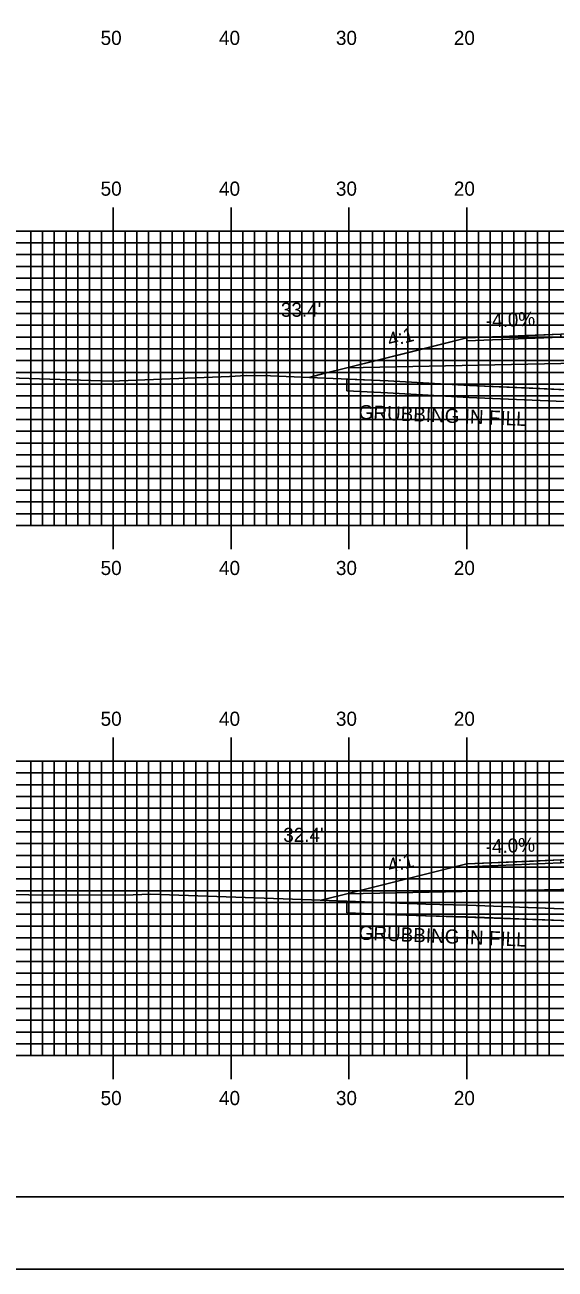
# Model space of a CAD drawing. Extents: x 1772022 to 1772366, y 442591 to 442811.
# Drawn here: x 1772130.6 to 1772175.6, y 442590.5 to 442696.2 of the extents above; entities that cross this region are included whole.
import ezdxf

# ---------------------------------------------------------------- set-up
doc = ezdxf.new("R2010")
doc.units = 0
for name, color, linetype in [('ANNOTATION', 7, 'Continuous'), ('BORDER', 7, 'Continuous'), ('D_Roadway_Centerline', 7, 'Continuous'), ('D_Roadway_Edge_Shoulder', 7, 'Continuous'), ('D_Roadway_SlopeLines', 7, 'Continuous'), ('D_Roadway_SubGrade', 7, 'Continuous'), ('D_Text_Standard', 7, 'Continuous'), ('GRUBBING IN FILL', 7, 'Continuous'), ('H_V ANNOTATION', 7, 'Continuous'), ('MAJOR', 7, 'Continuous'), ('MINOR', 7, 'Continuous'), ('PLOT BOUNDARY', 7, 'Continuous'), ('S_Roadway_Centerline', 7, 'Continuous')]:
    doc.layers.add(name, color=color, linetype=linetype)

msp = doc.modelspace()

# ---------------------------------------------------------------- linework, layer by layer
at = {"layer": 'BORDER'}
msp.add_lwpolyline([(1772038.49, 442596.67), (1772358.49, 442596.67), (1772358.49, 442806.67), (1772038.49, 442806.67)], close=True, dxfattribs=at)
at = {"layer": 'D_Roadway_Centerline'}
for points in [[(1772154.69, 442666.25), (1772156.09, 442666.6), (1772157.92, 442667.06), (1772163.4, 442668.42), (1772168.09, 442669.6), (1772168.1, 442669.6), (1772174.09, 442669.84), (1772176.09, 442669.92), (1772188.09, 442670.16), (1772191.75, 442670.09), (1772200.09, 442669.92), (1772200.09, 442669.92), (1772207.47, 442669.62), (1772208.09, 442669.6), (1772218.27, 442667.06), (1772232.78, 442663.43)], [(1772155.74, 442621.87), (1772156.09, 442621.96), (1772157.92, 442622.41), (1772157.92, 442622.41), (1772168.09, 442624.96), (1772173.77, 442625.18), (1772176.09, 442625.28), (1772176.09, 442625.28), (1772181.71, 442625.39), (1772188.09, 442625.52), (1772188.09, 442625.52), (1772188.09, 442625.52), (1772200.09, 442625.28), (1772200.1, 442625.28), (1772208.09, 442624.96), (1772214.34, 442623.39), (1772218.27, 442622.41), (1772218.27, 442622.41), (1772233.13, 442618.7)]]:
    msp.add_lwpolyline(points, dxfattribs=at)
at = {"layer": 'D_Roadway_Edge_Shoulder'}
for points in [[(1772176.09, 442669.92), (1772168.09, 442669.6), (1772168.09, 442669.35), (1772176.09, 442669.67)], [(1772176.09, 442625.28), (1772168.09, 442624.96), (1772168.09, 442624.71), (1772176.09, 442625.03)]]:
    msp.add_lwpolyline(points, close=True, dxfattribs=at)
at = {"layer": 'D_Roadway_SlopeLines'}
for points in [[(1772168.09, 442669.6), (1772157.92, 442667.06), (1772156.09, 442666.6), (1772154.69, 442666.25)], [(1772168.09, 442624.96), (1772157.92, 442622.41), (1772156.09, 442621.96), (1772155.74, 442621.87)]]:
    msp.add_lwpolyline(points, dxfattribs=at)
at = {"layer": 'D_Roadway_SubGrade'}
for points in [[(1772176.09, 442667.42), (1772157.92, 442667.06), (1772168.09, 442669.6), (1772168.09, 442669.35), (1772176.09, 442669.67), (1772188.09, 442669.91), (1772200.09, 442669.67), (1772208.09, 442669.35), (1772208.09, 442669.6), (1772218.27, 442667.06), (1772200.09, 442667.42), (1772188.09, 442667.66)], [(1772176.09, 442622.78), (1772157.92, 442622.41), (1772168.09, 442624.96), (1772168.09, 442624.71), (1772176.09, 442625.03), (1772188.09, 442625.27), (1772200.09, 442625.03), (1772208.09, 442624.71), (1772208.09, 442624.96), (1772218.27, 442622.41), (1772200.09, 442622.78), (1772188.09, 442623.02)]]:
    msp.add_lwpolyline(points, close=True, dxfattribs=at)
at = {"layer": 'GRUBBING IN FILL'}
for p, q in [((1772157.92, 442666.11), (1772157.92, 442665.11)), ((1772157.92, 442666.11), (1772157.92, 442665.11)), ((1772157.92, 442621.79), (1772157.92, 442620.79)), ((1772157.92, 442621.79), (1772157.92, 442620.79))]:
    msp.add_line(p, q, dxfattribs=at)
for points in [[(1772157.92, 442665.11), (1772161.37, 442664.95), (1772164.82, 442664.75), (1772168.27, 442664.55), (1772173.66, 442664.32), (1772179.06, 442664.09), (1772187.46, 442663.89), (1772188.09, 442663.88), (1772188.09, 442664.88), (1772184.93, 442664.92), (1772182.01, 442665), (1772179.09, 442665.09), (1772173.71, 442665.32), (1772168.32, 442665.55), (1772164.87, 442665.75), (1772161.42, 442665.95), (1772157.92, 442666.11)], [(1772157.92, 442665.11), (1772161.37, 442664.95), (1772164.82, 442664.75), (1772168.27, 442664.55), (1772173.66, 442664.32), (1772179.06, 442664.09), (1772187.46, 442663.89), (1772188.09, 442663.88), (1772188.09, 442664.88), (1772184.93, 442664.92), (1772182.01, 442665), (1772179.09, 442665.09), (1772173.71, 442665.32), (1772168.32, 442665.55), (1772164.87, 442665.75), (1772161.42, 442665.95), (1772157.92, 442666.11)], [(1772157.92, 442620.79), (1772161.25, 442620.66), (1772166.35, 442620.49), (1772176.93, 442620.1), (1772185.74, 442619.76), (1772188.09, 442619.63), (1772188.09, 442620.63), (1772185.79, 442620.76), (1772176.97, 442621.1), (1772168.15, 442621.44), (1772164.61, 442621.54), (1772157.92, 442621.79)], [(1772157.92, 442620.79), (1772161.25, 442620.66), (1772166.35, 442620.49), (1772176.93, 442620.1), (1772185.74, 442619.76), (1772188.09, 442619.63), (1772188.09, 442620.63), (1772185.79, 442620.76), (1772176.97, 442621.1), (1772168.15, 442621.44), (1772164.61, 442621.54), (1772157.92, 442621.79)]]:
    msp.add_lwpolyline(points, close=True, dxfattribs=at)
for points in [[(1772157.92, 442665.11), (1772161.37, 442664.95), (1772168.27, 442664.55), (1772179.06, 442664.09), (1772184.91, 442663.92), (1772190.01, 442663.85), (1772197.05, 442663.74), (1772205.6, 442663.11), (1772210.14, 442662.86), (1772218.27, 442662.71)], [(1772157.92, 442665.11), (1772161.37, 442664.95), (1772168.27, 442664.55), (1772179.06, 442664.09), (1772184.91, 442663.92), (1772190.01, 442663.85), (1772197.05, 442663.74), (1772205.6, 442663.11), (1772210.14, 442662.86), (1772218.27, 442662.71)], [(1772157.92, 442620.79), (1772164.58, 442620.54), (1772168.12, 442620.44), (1772185.74, 442619.76), (1772189.33, 442619.56), (1772194.53, 442619.18), (1772202.12, 442618.6), (1772207.18, 442618.79), (1772218.27, 442618.48)], [(1772157.92, 442620.79), (1772164.58, 442620.54), (1772168.12, 442620.44), (1772185.74, 442619.76), (1772189.33, 442619.56), (1772194.53, 442619.18), (1772202.12, 442618.6), (1772207.18, 442618.79), (1772218.27, 442618.48)]]:
    msp.add_lwpolyline(points, dxfattribs=at)
at = {"layer": 'MAJOR'}
for p, q in [((1772138.09, 442680.67), (1772138.09, 442678.67)), ((1772148.09, 442680.67), (1772148.09, 442678.67)), ((1772158.09, 442680.67), (1772158.09, 442678.67)), ((1772168.09, 442680.67), (1772168.09, 442678.67)), ((1772048.09, 442678.67), (1772328.09, 442678.67)), ((1772048.09, 442678.67), (1772328.09, 442678.67)), ((1772138.09, 442653.67), (1772138.09, 442678.67)), ((1772148.09, 442653.67), (1772148.09, 442678.67)), ((1772158.09, 442653.67), (1772158.09, 442678.67)), ((1772168.09, 442653.67), (1772168.09, 442678.67)), ((1772048.09, 442673.67), (1772328.09, 442673.67)), ((1772048.09, 442668.67), (1772328.09, 442668.67)), ((1772048.09, 442663.67), (1772328.09, 442663.67)), ((1772048.09, 442658.67), (1772328.09, 442658.67)), ((1772048.09, 442653.67), (1772328.09, 442653.67)), ((1772048.09, 442653.67), (1772328.09, 442653.67)), ((1772138.09, 442651.66), (1772138.09, 442653.67)), ((1772148.09, 442651.66), (1772148.09, 442653.67)), ((1772158.09, 442651.66), (1772158.09, 442653.67)), ((1772168.09, 442651.66), (1772168.09, 442653.67)), ((1772138.09, 442635.67), (1772138.09, 442633.67)), ((1772148.09, 442635.67), (1772148.09, 442633.67)), ((1772158.09, 442635.67), (1772158.09, 442633.67)), ((1772168.09, 442635.67), (1772168.09, 442633.67)), ((1772048.09, 442633.67), (1772328.09, 442633.67)), ((1772048.09, 442633.67), (1772328.09, 442633.67)), ((1772138.09, 442608.67), (1772138.09, 442633.67)), ((1772148.09, 442608.67), (1772148.09, 442633.67)), ((1772158.09, 442608.67), (1772158.09, 442633.67)), ((1772168.09, 442608.67), (1772168.09, 442633.67)), ((1772048.09, 442628.67), (1772328.09, 442628.67)), ((1772048.09, 442623.67), (1772328.09, 442623.67)), ((1772048.09, 442618.67), (1772328.09, 442618.67)), ((1772048.09, 442613.67), (1772328.09, 442613.67)), ((1772048.09, 442608.67), (1772328.09, 442608.67)), ((1772048.09, 442608.67), (1772328.09, 442608.67)), ((1772138.09, 442606.66), (1772138.09, 442608.67)), ((1772148.09, 442606.66), (1772148.09, 442608.67)), ((1772158.09, 442606.66), (1772158.09, 442608.67)), ((1772168.09, 442606.66), (1772168.09, 442608.67))]:
    msp.add_line(p, q, dxfattribs=at)
at = {"layer": 'MINOR'}
for p, q in [((1772131.09, 442653.67), (1772131.09, 442678.67)), ((1772132.09, 442653.67), (1772132.09, 442678.67)), ((1772133.09, 442653.67), (1772133.09, 442678.67)), ((1772134.09, 442653.67), (1772134.09, 442678.67)), ((1772135.09, 442653.67), (1772135.09, 442678.67)), ((1772136.09, 442653.67), (1772136.09, 442678.67)), ((1772137.09, 442653.67), (1772137.09, 442678.67)), ((1772139.09, 442653.67), (1772139.09, 442678.67)), ((1772140.09, 442653.67), (1772140.09, 442678.67)), ((1772141.09, 442653.67), (1772141.09, 442678.67)), ((1772142.09, 442653.67), (1772142.09, 442678.67)), ((1772143.09, 442653.67), (1772143.09, 442678.67)), ((1772144.09, 442653.67), (1772144.09, 442678.67)), ((1772145.09, 442653.67), (1772145.09, 442678.67)), ((1772146.09, 442653.67), (1772146.09, 442678.67)), ((1772147.09, 442653.67), (1772147.09, 442678.67)), ((1772149.09, 442653.67), (1772149.09, 442678.67)), ((1772150.09, 442653.67), (1772150.09, 442678.67)), ((1772151.09, 442653.67), (1772151.09, 442678.67)), ((1772152.09, 442653.67), (1772152.09, 442678.67)), ((1772153.09, 442653.67), (1772153.09, 442678.67)), ((1772154.09, 442653.67), (1772154.09, 442678.67)), ((1772155.09, 442653.67), (1772155.09, 442678.67)), ((1772156.09, 442653.67), (1772156.09, 442678.67)), ((1772157.09, 442653.67), (1772157.09, 442678.67)), ((1772159.09, 442653.67), (1772159.09, 442678.67)), ((1772160.09, 442653.67), (1772160.09, 442678.67)), ((1772161.09, 442653.67), (1772161.09, 442678.67)), ((1772162.09, 442653.67), (1772162.09, 442678.67)), ((1772163.09, 442653.67), (1772163.09, 442678.67)), ((1772164.09, 442653.67), (1772164.09, 442678.67)), ((1772165.09, 442653.67), (1772165.09, 442678.67)), ((1772166.09, 442653.67), (1772166.09, 442678.67)), ((1772167.09, 442653.67), (1772167.09, 442678.67)), ((1772169.09, 442653.67), (1772169.09, 442678.67)), ((1772170.09, 442653.67), (1772170.09, 442678.67)), ((1772171.09, 442653.67), (1772171.09, 442678.67)), ((1772172.09, 442653.67), (1772172.09, 442678.67)), ((1772173.09, 442653.67), (1772173.09, 442678.67)), ((1772174.09, 442653.67), (1772174.09, 442678.67)), ((1772175.09, 442653.67), (1772175.09, 442678.67)), ((1772048.09, 442677.67), (1772328.09, 442677.67)), ((1772048.09, 442676.67), (1772328.09, 442676.67)), ((1772048.09, 442675.67), (1772328.09, 442675.67)), ((1772048.09, 442674.67), (1772328.09, 442674.67)), ((1772048.09, 442672.67), (1772328.09, 442672.67)), ((1772048.09, 442671.67), (1772328.09, 442671.67)), ((1772048.09, 442670.67), (1772328.09, 442670.67)), ((1772048.09, 442669.67), (1772328.09, 442669.67)), ((1772048.09, 442667.67), (1772328.09, 442667.67)), ((1772048.09, 442666.67), (1772328.09, 442666.67)), ((1772048.09, 442665.67), (1772328.09, 442665.67)), ((1772048.09, 442664.67), (1772328.09, 442664.67)), ((1772048.09, 442662.67), (1772328.09, 442662.67)), ((1772048.09, 442661.67), (1772328.09, 442661.67)), ((1772048.09, 442660.67), (1772328.09, 442660.67)), ((1772048.09, 442659.67), (1772328.09, 442659.67)), ((1772048.09, 442657.67), (1772328.09, 442657.67)), ((1772048.09, 442656.67), (1772328.09, 442656.67)), ((1772048.09, 442655.67), (1772328.09, 442655.67)), ((1772048.09, 442654.67), (1772328.09, 442654.67)), ((1772131.09, 442608.67), (1772131.09, 442633.67)), ((1772132.09, 442608.67), (1772132.09, 442633.67)), ((1772133.09, 442608.67), (1772133.09, 442633.67)), ((1772134.09, 442608.67), (1772134.09, 442633.67)), ((1772135.09, 442608.67), (1772135.09, 442633.67)), ((1772136.09, 442608.67), (1772136.09, 442633.67)), ((1772137.09, 442608.67), (1772137.09, 442633.67)), ((1772139.09, 442608.67), (1772139.09, 442633.67)), ((1772140.09, 442608.67), (1772140.09, 442633.67)), ((1772141.09, 442608.67), (1772141.09, 442633.67)), ((1772142.09, 442608.67), (1772142.09, 442633.67)), ((1772143.09, 442608.67), (1772143.09, 442633.67)), ((1772144.09, 442608.67), (1772144.09, 442633.67)), ((1772145.09, 442608.67), (1772145.09, 442633.67)), ((1772146.09, 442608.67), (1772146.09, 442633.67)), ((1772147.09, 442608.67), (1772147.09, 442633.67)), ((1772149.09, 442608.67), (1772149.09, 442633.67)), ((1772150.09, 442608.67), (1772150.09, 442633.67)), ((1772151.09, 442608.67), (1772151.09, 442633.67)), ((1772152.09, 442608.67), (1772152.09, 442633.67)), ((1772153.09, 442608.67), (1772153.09, 442633.67)), ((1772154.09, 442608.67), (1772154.09, 442633.67)), ((1772155.09, 442608.67), (1772155.09, 442633.67)), ((1772156.09, 442608.67), (1772156.09, 442633.67)), ((1772157.09, 442608.67), (1772157.09, 442633.67)), ((1772159.09, 442608.67), (1772159.09, 442633.67)), ((1772160.09, 442608.67), (1772160.09, 442633.67)), ((1772161.09, 442608.67), (1772161.09, 442633.67)), ((1772162.09, 442608.67), (1772162.09, 442633.67)), ((1772163.09, 442608.67), (1772163.09, 442633.67)), ((1772164.09, 442608.67), (1772164.09, 442633.67)), ((1772165.09, 442608.67), (1772165.09, 442633.67)), ((1772166.09, 442608.67), (1772166.09, 442633.67)), ((1772167.09, 442608.67), (1772167.09, 442633.67)), ((1772169.09, 442608.67), (1772169.09, 442633.67)), ((1772170.09, 442608.67), (1772170.09, 442633.67)), ((1772171.09, 442608.67), (1772171.09, 442633.67)), ((1772172.09, 442608.67), (1772172.09, 442633.67)), ((1772173.09, 442608.67), (1772173.09, 442633.67)), ((1772174.09, 442608.67), (1772174.09, 442633.67)), ((1772175.09, 442608.67), (1772175.09, 442633.67)), ((1772048.09, 442632.67), (1772328.09, 442632.67)), ((1772048.09, 442631.67), (1772328.09, 442631.67)), ((1772048.09, 442630.67), (1772328.09, 442630.67)), ((1772048.09, 442629.67), (1772328.09, 442629.67)), ((1772048.09, 442627.67), (1772328.09, 442627.67)), ((1772048.09, 442626.67), (1772328.09, 442626.67)), ((1772048.09, 442625.67), (1772328.09, 442625.67)), ((1772048.09, 442624.67), (1772328.09, 442624.67)), ((1772048.09, 442622.67), (1772328.09, 442622.67)), ((1772048.09, 442621.67), (1772328.09, 442621.67)), ((1772048.09, 442620.67), (1772328.09, 442620.67)), ((1772048.09, 442619.67), (1772328.09, 442619.67)), ((1772048.09, 442617.67), (1772328.09, 442617.67)), ((1772048.09, 442616.67), (1772328.09, 442616.67)), ((1772048.09, 442615.67), (1772328.09, 442615.67)), ((1772048.09, 442614.67), (1772328.09, 442614.67)), ((1772048.09, 442612.67), (1772328.09, 442612.67)), ((1772048.09, 442611.67), (1772328.09, 442611.67)), ((1772048.09, 442610.67), (1772328.09, 442610.67)), ((1772048.09, 442609.67), (1772328.09, 442609.67))]:
    msp.add_line(p, q, dxfattribs=at)
at = {"layer": 'PLOT BOUNDARY'}
msp.add_lwpolyline([(1772022.31, 442590.55), (1772362.31, 442590.55), (1772362.31, 442810.55), (1772022.31, 442810.55)], close=True, dxfattribs=at)
at = {"layer": 'S_Roadway_Centerline'}
for points in [[(1772126.59, 442666.3), (1772137.91, 442665.93), (1772147.95, 442666.32), (1772149.38, 442666.41), (1772151.44, 442666.39), (1772161.42, 442665.95), (1772168.32, 442665.55), (1772179.09, 442665.09), (1772184.93, 442664.92), (1772190.02, 442664.85), (1772197.09, 442664.74), (1772205.67, 442664.1), (1772210.18, 442663.86), (1772227.84, 442663.54), (1772231.31, 442663.51), (1772231.8, 442663.47), (1772232.48, 442663.44), (1772251.4, 442662.74)], [(1772122.77, 442622.34), (1772139.06, 442622.29), (1772141.24, 442622.37), (1772154.91, 442621.9), (1772164.61, 442621.54), (1772168.15, 442621.44), (1772185.79, 442620.76), (1772189.4, 442620.56), (1772194.61, 442620.18), (1772202.14, 442619.61), (1772207.18, 442619.79), (1772221.15, 442619.4), (1772226.33, 442619.05), (1772236.06, 442618.55), (1772246.73, 442618.04)]]:
    msp.add_lwpolyline(points, dxfattribs=at)

# ---------------------------------------------------------------- texts
at = {"layer": 'ANNOTATION'}
for s, rotation, p in [('-4.0%', 2.2905, (1772169.73, 442670.47)), ('4:1', 14.039, (1772161.54, 442668.82)), ('-4.0%', 2.2909, (1772169.72, 442625.82)), ('4:1', 14.0328, (1772161.54, 442624.18))]:
    msp.add_text(s, height=1.2, rotation=rotation, dxfattribs=at).set_placement(p)
at = {"layer": 'D_Text_Standard'}
for s, p in [("33.4'", (1772152.32, 442671.39)), ("32.4'", (1772152.52, 442626.81))]:
    msp.add_text(s, height=1.2, dxfattribs=at).set_placement(p)
at = {"layer": 'GRUBBING IN FILL'}
for p in [(1772158.9, 442662.72), (1772158.9, 442618.52)]:
    msp.add_text('GRUBBING IN FILL', height=1.2, rotation=357.5719, dxfattribs=at).set_placement(p)
at = {"layer": 'H_V ANNOTATION'}
for s, p in [('50', (1772137.02, 442694.47)), ('40', (1772147.07, 442694.47)), ('30', (1772156.99, 442694.47)), ('20', (1772167, 442694.47)), ('50', (1772137.02, 442681.67)), ('40', (1772147.07, 442681.67)), ('30', (1772156.99, 442681.67)), ('20', (1772167, 442681.67)), ('50', (1772137.02, 442649.47)), ('40', (1772147.07, 442649.47)), ('30', (1772156.99, 442649.47)), ('20', (1772167, 442649.47)), ('50', (1772137.02, 442636.67)), ('40', (1772147.07, 442636.67)), ('30', (1772156.99, 442636.67)), ('20', (1772167, 442636.67)), ('50', (1772137.02, 442604.47)), ('40', (1772147.07, 442604.47)), ('30', (1772156.99, 442604.47)), ('20', (1772167, 442604.47))]:
    msp.add_text(s, height=1.2, dxfattribs=at).set_placement(p)

doc.saveas('drawing.dxf')
